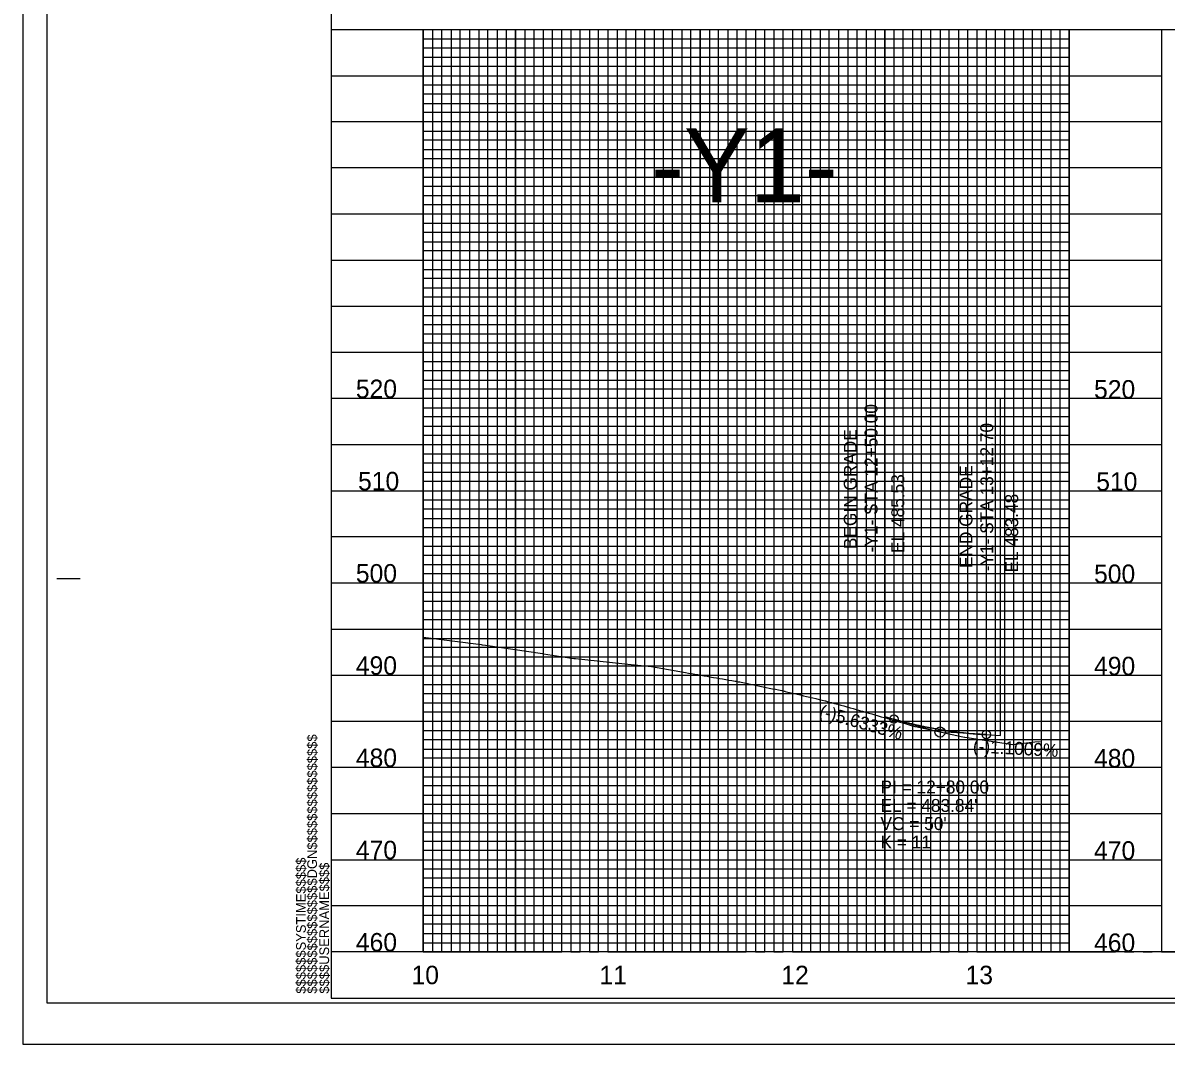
# Model space of a CAD drawing. Extents: x 571503 to 593215, y -77195 to -51828.
# Drawn here: x 582330 to 582949, y -75605 to -75051 of the extents above; entities that cross this region are included whole.
import ezdxf

# ---------------------------------------------------------------- set-up
doc = ezdxf.new("R2010")
doc.units = 0
for name, color, linetype in [('Exist Vertical Profile Ground Line', 7, 'Continuous'), ('Exist Vertical Profile Horizontal Axis Label Major', 7, 'Continuous'), ('Exist Vertical Profile Vertical Axis Label', 7, 'Continuous'), ('Prop PFL Text', 7, 'Continuous'), ('Prop Vertical Profile Curve Label', 7, 'Continuous'), ('Prop Vertical Profile Grade', 7, 'Continuous'), ('Prop Vertical Profile Grade Label', 7, 'Continuous'), ('Prop VPI Label', 7, 'Continuous'), ('Sheet Cutting Line CELL', 7, 'Continuous'), ('Sheet DOT Grid CELL', 7, 'Continuous'), ('Sheet Layout Profile Border Port 2', 7, 'Continuous'), ('Sheet Plot Border Inside CELL', 7, 'Continuous'), ('Sheet Plot Border Outside CELL', 7, 'Continuous'), ('Sheet Profile CELL', 7, 'Continuous'), ('Sheet Profile Grid Major CELL', 7, 'Continuous'), ('Sheet Profile Grid Middle CELL', 7, 'Continuous'), ('Sheet Profile Grid Minor CELL', 7, 'Continuous')]:
    doc.layers.add(name, color=color, linetype=linetype)

msp = doc.modelspace()

# ---------------------------------------------------------------- linework, layer by layer
at = {"layer": 'Exist Vertical Profile Ground Line'}
for points in [[(582546.98, -75384.54), (582578.29, -75388.57), (582578.94, -75388.65), (582580.68, -75388.87), (582611.64, -75393.46), (582611.65, -75393.47), (582612.17, -75393.54), (582628.61, -75396), (582629.52, -75396.11), (582661.19, -75399.46), (582661.41, -75399.49), (582670.54, -75400.46), (582670.58, -75400.46), (582688.97, -75403.68), (582690.65, -75403.97), (582692.34, -75404.26), (582694.02, -75404.56), (582695.71, -75404.85), (582697.39, -75405.15), (582699.07, -75405.44), (582700.76, -75405.73), (582701.53, -75405.87), (582702.44, -75406.02), (582703.17, -75406.14), (582704.13, -75406.31), (582705.81, -75406.6), (582707.49, -75406.9), (582709.18, -75407.19), (582710.86, -75407.48), (582712.55, -75407.78), (582714.23, -75408.07), (582715.92, -75408.37), (582716.27, -75408.43), (582717.6, -75408.67), (582718.09, -75408.75), (582718.42, -75408.82), (582719.28, -75409), (582720.97, -75409.34), (582722.65, -75409.68), (582724.34, -75410.02), (582726.02, -75410.37), (582727.71, -75410.71), (582729.39, -75411.06), (582731.07, -75411.41), (582732.76, -75411.75), (582734.44, -75412.1), (582736.13, -75412.45), (582737.81, -75412.8), (582739.5, -75413.15), (582741.18, -75413.5), (582742.51, -75413.78), (582742.86, -75413.88), (582743.03, -75413.93), (582744.55, -75414.28), (582746.23, -75414.67), (582747.92, -75415.06), (582749.6, -75415.45), (582751.29, -75415.85), (582752.97, -75416.24), (582754.65, -75416.64), (582756.34, -75417.04), (582758.02, -75417.43), (582759.71, -75417.83), (582761.39, -75418.24), (582763.08, -75418.64), (582764.76, -75419.04), (582764.87, -75419.07), (582766.44, -75419.53), (582766.97, -75419.69), (582768.13, -75420.01), (582768.68, -75420.16), (582769.81, -75420.47), (582771.5, -75420.92), (582773.18, -75421.37), (582774.86, -75421.83), (582776.55, -75422.29), (582777.75, -75422.62), (582778.23, -75422.76), (582779.92, -75423.24), (582781.6, -75423.73), (582783.29, -75424.21), (582784.97, -75424.7), (582786.65, -75425.19), (582788.34, -75425.67), (582790.02, -75426.16), (582791.71, -75426.65), (582793.39, -75427.14), (582795.08, -75427.63), (582796.76, -75428.11), (582798.13, -75428.51), (582798.44, -75428.59), (582798.63, -75428.63), (582800.13, -75429.07), (582801.81, -75429.56), (582803.5, -75430.05), (582805.18, -75430.54), (582806.87, -75431.04), (582808.55, -75431.53), (582810.23, -75432.02), (582811.92, -75432.52), (582811.98, -75432.54)], [(582811.98, -75432.54), (582813.24, -75432.92), (582813.41, -75432.96), (582813.6, -75433), (582815.29, -75433.36), (582816.97, -75433.72), (582818.66, -75434.09), (582820.34, -75434.45), (582839.28, -75438.56), (582840.19, -75438.75), (582840.43, -75438.73), (582866.36, -75442.67), (582867.62, -75442.56), (582869.06, -75442.36), (582878.4, -75441.23), (582881.23, -75441.07)]]:
    msp.add_lwpolyline(points, dxfattribs=at)
at = {"layer": 'Prop PFL Text'}
for p, q in [((582796.98, -75427.51), (582796.98, -75244.45)), ((582859.68, -75437.76), (582859.68, -75254.7))]:
    msp.add_line(p, q, dxfattribs=at)
at = {"layer": 'Prop Vertical Profile Curve Label'}
for centre in [(582801.98, -75428.92), (582851.98, -75437.34)]:
    msp.add_circle(centre, 2.25, dxfattribs=at)
at = {"layer": 'Prop Vertical Profile Grade'}
for p, q in [((582796.98, -75427.51), (582801.98, -75428.92)), ((582851.98, -75437.34), (582859.68, -75437.76))]:
    msp.add_line(p, q, dxfattribs=at)
msp.add_spline([(582801.98, -75428.92), (582802.98, -75429.2), (582803.98, -75429.47), (582804.98, -75429.74), (582805.98, -75430.01), (582806.98, -75430.27), (582807.98, -75430.53), (582808.98, -75430.78), (582809.98, -75431.03), (582810.98, -75431.27), (582811.98, -75431.51), (582812.98, -75431.74), (582813.98, -75431.97), (582814.98, -75432.2), (582815.98, -75432.42), (582816.98, -75432.64), (582817.98, -75432.85), (582818.98, -75433.05), (582819.98, -75433.26), (582820.98, -75433.45), (582821.98, -75433.65), (582822.98, -75433.84), (582823.98, -75434.02), (582824.98, -75434.2), (582825.98, -75434.37), (582826.98, -75434.55), (582827.98, -75434.71), (582828.98, -75434.87), (582829.98, -75435.03), (582830.98, -75435.18), (582831.98, -75435.33), (582832.98, -75435.47), (582833.98, -75435.61), (582834.98, -75435.75), (582835.98, -75435.88), (582836.98, -75436), (582837.98, -75436.12), (582838.98, -75436.24), (582839.98, -75436.35), (582840.98, -75436.46), (582841.98, -75436.56), (582842.98, -75436.66), (582843.98, -75436.75), (582844.98, -75436.84), (582845.98, -75436.93), (582846.98, -75437.01), (582847.98, -75437.08), (582848.98, -75437.15), (582849.98, -75437.22), (582850.98, -75437.28), (582851.98, -75437.34)], degree=3, dxfattribs=at)
at = {"layer": 'Prop VPI Label'}
for p, q in [((582801.98, -75428.92), (582824.34, -75435.22)), ((582851.98, -75437.34), (582829.73, -75436.11))]:
    msp.add_line(p, q, dxfattribs=at)
msp.add_circle((582826.98, -75435.96), 2.75, dxfattribs=at)
at = {"layer": 'Sheet Cutting Line CELL'}
for p, q in [((582329.98, -74505.16), (582329.98, -75605.16)), ((582329.98, -75605.16), (584013.98, -75605.16))]:
    msp.add_line(p, q, dxfattribs=at)
at = {"layer": 'Sheet DOT Grid CELL'}
for p, q in [((582496.98, -75055.16), (583996.87, -75055.16)), ((582546.98, -75055.16), (582546.98, -75555.16)), ((582596.98, -75055.16), (582596.98, -75555.16)), ((582646.98, -75055.16), (582646.98, -75555.16)), ((582696.98, -75055.16), (582696.98, -75555.16)), ((582746.98, -75055.16), (582746.98, -75555.16)), ((582796.98, -75055.16), (582796.98, -75555.16)), ((582846.98, -75055.16), (582846.98, -75555.16)), ((582896.98, -75055.16), (582896.98, -75555.16)), ((582946.98, -75055.16), (582946.98, -75555.16))]:
    msp.add_line(p, q, dxfattribs=at)
at = {"layer": 'Sheet Layout Profile Border Port 2'}
msp.add_lwpolyline([(582546.98, -75055.16), (583946.98, -75055.16), (583946.98, -75555.16), (582546.98, -75555.16)], close=True, dxfattribs=at)
at = {"layer": 'Sheet Plot Border Inside CELL'}
msp.add_lwpolyline([(582342.98, -75582.71), (584009.48, -75582.71), (584009.48, -74527.61), (582342.98, -74527.61)], close=True, dxfattribs=at)
at = {"layer": 'Sheet Plot Border Outside CELL'}
msp.add_lwpolyline([(582329.98, -75605.16), (584013.98, -75605.16), (584013.98, -74505.16), (582329.98, -74505.16)], close=True, dxfattribs=at)
at = {"layer": 'Sheet Profile CELL'}
for p, q in [((582496.98, -75055.16), (583996.98, -75055.16)), ((582348.48, -75352.66), (582360.98, -75352.66)), ((583996.98, -75555.16), (582496.98, -75555.16)), ((582496.98, -75580.16), (583996.98, -75580.16)), ((582496.98, -75580.16), (582496.98, -75580.16)), ((582496.98, -75580.16), (582496.98, -75580.16)), ((582496.98, -75580.16), (582496.98, -75580.16)), ((582496.98, -75580.16), (582496.98, -75580.16)), ((582496.98, -75580.16), (582496.98, -75580.16)), ((582496.98, -75580.16), (582496.98, -75580.16)), ((582496.98, -75580.16), (582496.98, -75580.16))]:
    msp.add_line(p, q, dxfattribs=at)
msp.add_lwpolyline([(583996.98, -74530.16), (582496.98, -74530.16), (582496.98, -75580.16), (583996.98, -75580.16)], close=True, dxfattribs=at)
msp.add_lwpolyline([(582534.48, -75580.16), (582534.48, -75580.16)], dxfattribs=at)
at = {"layer": 'Sheet Profile Grid Major CELL'}
for p, q in [((582546.98, -75055.16), (582546.98, -75555.16)), ((582596.98, -75555.16), (582596.98, -75055.16)), ((582596.98, -75055.16), (582646.98, -75055.16)), ((582646.98, -75055.16), (582646.98, -75555.16)), ((582696.98, -75555.16), (582696.98, -75055.16)), ((582696.98, -75055.16), (582746.98, -75055.16)), ((582746.98, -75055.16), (582746.98, -75555.16)), ((582796.98, -75555.16), (582796.98, -75055.16)), ((582796.98, -75055.16), (582846.98, -75055.16)), ((582846.98, -75055.16), (582846.98, -75555.16)), ((582896.98, -75555.16), (582896.98, -75055.16)), ((582896.98, -75055.16), (582946.98, -75055.16)), ((582946.98, -75055.16), (582946.98, -75555.16)), ((582496.98, -75455.16), (582496.98, -75455.16)), ((582496.98, -75455.16), (582496.98, -75505.16)), ((582946.98, -75455.16), (582496.98, -75455.16)), ((582496.98, -75505.16), (582946.98, -75505.16)), ((582496.98, -75555.16), (582496.98, -75555.16)), ((582546.98, -75555.16), (582596.98, -75555.16)), ((582646.98, -75555.16), (582696.98, -75555.16)), ((582746.98, -75555.16), (582796.98, -75555.16)), ((582846.98, -75555.16), (582896.98, -75555.16)), ((582946.98, -75555.16), (582996.98, -75555.16))]:
    msp.add_line(p, q, dxfattribs=at)
for points in [[(582946.98, -75105.16), (582496.98, -75105.16)], [(582946.98, -75155.16), (582496.98, -75155.16), (582496.98, -75205.16), (582946.98, -75205.16)], [(582946.98, -75255.16), (582496.98, -75255.16), (582496.98, -75305.16), (582946.98, -75305.16)], [(582946.98, -75355.16), (582496.98, -75355.16), (582496.98, -75405.16), (582946.98, -75405.16)], [(583996.98, -75555.16), (582496.98, -75555.16)]]:
    msp.add_lwpolyline(points, dxfattribs=at)
at = {"layer": 'Sheet Profile Grid Middle CELL'}
for p, q in [((582521.98, -75055.16), (582571.98, -75055.16)), ((582571.98, -75055.16), (582571.98, -75555.16)), ((582621.98, -75555.16), (582621.98, -75055.16)), ((582621.98, -75055.16), (582671.98, -75055.16)), ((582671.98, -75055.16), (582671.98, -75555.16)), ((582721.98, -75555.16), (582721.98, -75055.16)), ((582721.98, -75055.16), (582771.98, -75055.16)), ((582771.98, -75055.16), (582771.98, -75555.16)), ((582821.98, -75555.16), (582821.98, -75055.16)), ((582821.98, -75055.16), (582871.98, -75055.16)), ((582871.98, -75055.16), (582871.98, -75555.16)), ((582921.98, -75055.16), (582971.98, -75055.16)), ((582571.98, -75555.16), (582621.98, -75555.16)), ((582671.98, -75555.16), (582721.98, -75555.16)), ((582771.98, -75555.16), (582821.98, -75555.16)), ((582871.98, -75555.16), (582921.98, -75555.16))]:
    msp.add_line(p, q, dxfattribs=at)
for points in [[(582496.98, -75080.16), (582946.98, -75080.16)], [(582946.98, -75130.16), (582496.98, -75130.16), (582496.98, -75180.16), (582946.98, -75180.16)], [(582946.98, -75230.16), (582496.98, -75230.16), (582496.98, -75280.16), (582946.98, -75280.16)], [(582946.98, -75330.16), (582496.98, -75330.16), (582496.98, -75380.16), (582946.98, -75380.16)], [(582946.98, -75430.16), (582496.98, -75430.16), (582496.98, -75480.16), (582946.98, -75480.16)], [(582946.98, -75530.16), (582496.98, -75530.16)]]:
    msp.add_lwpolyline(points, dxfattribs=at)
at = {"layer": 'Sheet Profile Grid Minor CELL'}
for p, q in [((582766.98, -75555.16), (582766.98, -75055.16)), ((582766.98, -75055.16), (582776.98, -75055.16)), ((582776.98, -75055.16), (582776.98, -75555.16)), ((582781.98, -75555.16), (582781.98, -75055.16)), ((582781.98, -75055.16), (582786.98, -75055.16)), ((582786.98, -75055.16), (582786.98, -75555.16)), ((582791.98, -75555.16), (582791.98, -75055.16)), ((582791.98, -75055.16), (582801.98, -75055.16)), ((582801.98, -75055.16), (582801.98, -75555.16)), ((582806.98, -75555.16), (582806.98, -75055.16)), ((582806.98, -75055.16), (582811.98, -75055.16)), ((582811.98, -75055.16), (582811.98, -75555.16)), ((582816.98, -75555.16), (582816.98, -75055.16)), ((582816.98, -75055.16), (582826.98, -75055.16)), ((582826.98, -75055.16), (582826.98, -75555.16)), ((582831.98, -75555.16), (582831.98, -75055.16)), ((582831.98, -75055.16), (582836.98, -75055.16)), ((582836.98, -75055.16), (582836.98, -75555.16)), ((582841.98, -75555.16), (582841.98, -75055.16)), ((582841.98, -75055.16), (582851.98, -75055.16)), ((582851.98, -75055.16), (582851.98, -75555.16)), ((582856.98, -75555.16), (582856.98, -75055.16)), ((582856.98, -75055.16), (582861.98, -75055.16)), ((582861.98, -75055.16), (582861.98, -75555.16)), ((582866.98, -75555.16), (582866.98, -75055.16)), ((582866.98, -75055.16), (582876.98, -75055.16)), ((582876.98, -75055.16), (582876.98, -75555.16)), ((582881.98, -75555.16), (582881.98, -75055.16)), ((582881.98, -75055.16), (582886.98, -75055.16)), ((582886.98, -75055.16), (582886.98, -75555.16)), ((582891.98, -75555.16), (582891.98, -75055.16)), ((582891.98, -75055.16), (582901.98, -75055.16)), ((582906.98, -75055.16), (582911.98, -75055.16)), ((582916.98, -75055.16), (582926.98, -75055.16)), ((582931.98, -75055.16), (582936.98, -75055.16)), ((582941.98, -75055.16), (582951.98, -75055.16)), ((582546.98, -75060.16), (582896.98, -75060.16)), ((582896.98, -75065.16), (582546.98, -75065.16)), ((582546.98, -75070.16), (582896.98, -75070.16)), ((582896.98, -75075.16), (582546.98, -75075.16)), ((582546.98, -75085.16), (582896.98, -75085.16)), ((582896.98, -75090.16), (582546.98, -75090.16)), ((582546.98, -75095.16), (582896.98, -75095.16)), ((582896.98, -75100.16), (582546.98, -75100.16)), ((582546.98, -75110.16), (582896.98, -75110.16)), ((582896.98, -75115.16), (582546.98, -75115.16)), ((582546.98, -75120.16), (582896.98, -75120.16)), ((582896.98, -75125.16), (582546.98, -75125.16)), ((582546.98, -75135.16), (582896.98, -75135.16)), ((582896.98, -75140.16), (582546.98, -75140.16)), ((582546.98, -75145.16), (582896.98, -75145.16)), ((582896.98, -75150.16), (582546.98, -75150.16)), ((582546.98, -75160.16), (582896.98, -75160.16)), ((582896.98, -75165.16), (582546.98, -75165.16)), ((582546.98, -75170.16), (582896.98, -75170.16)), ((582896.98, -75175.16), (582546.98, -75175.16)), ((582546.98, -75185.16), (582896.98, -75185.16)), ((582896.98, -75190.16), (582546.98, -75190.16)), ((582546.98, -75195.16), (582896.98, -75195.16)), ((582896.98, -75200.16), (582546.98, -75200.16)), ((582546.98, -75210.16), (582896.98, -75210.16)), ((582896.98, -75215.16), (582546.98, -75215.16)), ((582546.98, -75220.16), (582896.98, -75220.16)), ((582896.98, -75225.16), (582546.98, -75225.16)), ((582546.98, -75235.16), (582896.98, -75235.16)), ((582896.98, -75240.16), (582546.98, -75240.16)), ((582546.98, -75245.16), (582896.98, -75245.16)), ((582896.98, -75250.05), (582546.98, -75250.01)), ((582546.98, -75260.16), (582896.98, -75260.16)), ((582896.98, -75265.16), (582546.98, -75265.16)), ((582546.98, -75270.16), (582896.98, -75270.16)), ((582896.98, -75275.16), (582546.98, -75275.16)), ((582546.98, -75285.16), (582896.98, -75285.16)), ((582896.98, -75290.16), (582546.98, -75290.16)), ((582546.98, -75295.16), (582896.98, -75295.16)), ((582896.98, -75300.16), (582546.98, -75300.16)), ((582546.98, -75310.16), (582896.98, -75310.16)), ((582896.98, -75315.16), (582546.98, -75315.16)), ((582546.98, -75320.16), (582896.98, -75320.16)), ((582896.98, -75325.16), (582546.98, -75325.16)), ((582546.98, -75335.16), (582896.98, -75335.16)), ((582896.98, -75340.16), (582546.98, -75340.16)), ((582546.98, -75345.16), (582896.98, -75345.16)), ((582896.98, -75350.16), (582546.98, -75350.16)), ((582546.98, -75360.16), (582896.98, -75360.16)), ((582896.98, -75365.16), (582546.98, -75365.16)), ((582546.98, -75370.16), (582896.98, -75370.16)), ((582896.98, -75375.16), (582546.98, -75375.16)), ((582546.98, -75385.16), (582896.98, -75385.16)), ((582896.98, -75390.16), (582546.98, -75390.16)), ((582546.98, -75395.16), (582896.98, -75395.16)), ((582896.98, -75400.16), (582546.98, -75400.16)), ((582546.98, -75410.16), (582896.98, -75410.16)), ((582896.98, -75415.16), (582546.98, -75415.16)), ((582546.98, -75420.16), (582896.98, -75420.16)), ((582896.98, -75425.16), (582546.98, -75425.16)), ((582546.98, -75435.16), (582896.98, -75435.16)), ((582896.98, -75440.16), (582546.98, -75440.16)), ((582546.98, -75445.16), (582896.98, -75445.16)), ((582896.98, -75450.16), (582546.98, -75450.16)), ((582546.98, -75460.16), (582896.98, -75460.16)), ((582896.98, -75465.16), (582546.98, -75465.16)), ((582546.98, -75470.16), (582896.98, -75470.16)), ((582896.98, -75475.16), (582546.98, -75475.16)), ((582546.98, -75485.16), (582896.98, -75485.16)), ((582896.98, -75490.16), (582546.98, -75490.16)), ((582546.98, -75495.16), (582896.98, -75495.16)), ((582896.98, -75500.16), (582546.98, -75500.16)), ((582546.98, -75510.16), (582896.98, -75510.16)), ((582896.98, -75515.16), (582546.98, -75515.16)), ((582546.98, -75520.16), (582896.98, -75520.16)), ((582896.98, -75525.16), (582546.98, -75525.16)), ((582546.98, -75535.16), (582896.98, -75535.16)), ((582896.98, -75540.16), (582546.98, -75540.16)), ((582546.98, -75545.16), (582896.98, -75545.16)), ((582546.98, -75550.16), (582896.98, -75550.16)), ((582761.98, -75555.16), (582766.98, -75555.16)), ((582776.98, -75555.16), (582781.98, -75555.16)), ((582786.98, -75555.16), (582791.98, -75555.16)), ((582801.98, -75555.16), (582806.98, -75555.16)), ((582811.98, -75555.16), (582816.98, -75555.16)), ((582826.98, -75555.16), (582831.98, -75555.16)), ((582836.98, -75555.16), (582841.98, -75555.16)), ((582851.98, -75555.16), (582856.98, -75555.16)), ((582861.98, -75555.16), (582866.98, -75555.16)), ((582876.98, -75555.16), (582881.98, -75555.16)), ((582886.98, -75555.16), (582891.98, -75555.16)), ((582901.98, -75555.16), (582906.98, -75555.16)), ((582911.98, -75555.16), (582916.98, -75555.16)), ((582926.98, -75555.16), (582931.98, -75555.16)), ((582936.98, -75555.16), (582941.98, -75555.16))]:
    msp.add_line(p, q, dxfattribs=at)
for points in [[(582546.98, -75055.16), (582551.98, -75055.16), (582551.98, -75555.16), (582556.98, -75555.16), (582556.98, -75055.16), (582561.98, -75055.16), (582561.98, -75555.16), (582566.98, -75555.16), (582566.98, -75055.16), (582576.98, -75055.16), (582576.98, -75555.16), (582581.98, -75555.16), (582581.98, -75055.16), (582586.98, -75055.16), (582586.98, -75555.16), (582591.98, -75555.16), (582601.98, -75555.16), (582606.98, -75555.16), (582606.98, -75055.16), (582611.98, -75055.16), (582611.98, -75555.16), (582616.98, -75555.16), (582616.98, -75055.16), (582626.98, -75055.16), (582626.98, -75555.16), (582631.98, -75555.16), (582631.98, -75055.16), (582636.98, -75055.16), (582636.98, -75555.16), (582641.98, -75555.16), (582641.98, -75055.16), (582651.98, -75055.16), (582651.98, -75555.16), (582656.98, -75555.16), (582656.98, -75055.16), (582661.98, -75055.16), (582661.98, -75555.16), (582666.98, -75555.16), (582666.98, -75055.16), (582676.98, -75055.16), (582676.98, -75555.16), (582681.98, -75555.16), (582681.98, -75055.16), (582686.98, -75055.16), (582686.98, -75555.16), (582691.98, -75555.16), (582691.98, -75055.16), (582701.98, -75055.16), (582701.98, -75555.16), (582706.98, -75555.16), (582706.98, -75055.16), (582711.98, -75055.16), (582711.98, -75555.16), (582716.98, -75555.16), (582716.98, -75055.16), (582726.98, -75055.16), (582726.98, -75555.16), (582731.98, -75555.16), (582731.98, -75055.16), (582736.98, -75055.16), (582736.98, -75555.16), (582741.98, -75555.16), (582741.98, -75055.16), (582751.98, -75055.16), (582751.98, -75555.16), (582756.98, -75555.16), (582756.98, -75055.16), (582761.98, -75055.16), (582761.98, -75555.16)], [(582591.98, -75555.16), (582591.98, -75055.16), (582601.98, -75055.16), (582601.98, -75555.16)]]:
    msp.add_lwpolyline(points, dxfattribs=at)

# ---------------------------------------------------------------- texts
at = {"layer": 'Exist Vertical Profile Horizontal Axis Label Major'}
for s, p in [('10', (582540.57, -75572.66)), ('11', (582642.41, -75572.66)), ('12', (582740.95, -75572.66)), ('13', (582840.79, -75572.66))]:
    msp.add_text(s, height=10, dxfattribs=at).set_placement(p)
at = {"layer": 'Exist Vertical Profile Vertical Axis Label'}
for s, height, p in [('-Y1-', 40, (582670.4, -75148.75)), ('520', 10, (582510.42, -75254.91)), ('520', 10, (582910.42, -75255.16)), ('510', 10, (582511.61, -75304.91)), ('510', 10, (582911.61, -75305.16)), ('500', 10, (582510.42, -75354.91)), ('500', 10, (582910.42, -75355.16)), ('490', 10, (582510.42, -75404.91)), ('490', 10, (582910.42, -75405.16)), ('480', 10, (582510.42, -75454.91)), ('480', 10, (582910.42, -75455.16)), ('470', 10, (582510.42, -75504.91)), ('470', 10, (582910.42, -75505.16)), ('460', 10, (582510.42, -75554.91)), ('460', 10, (582910.42, -75555.16))]:
    msp.add_text(s, height=height, dxfattribs=at).set_placement(p)
at = {"layer": 'Prop PFL Text'}
for s, p in [('-Y1- STA 12+50.00', (582793.09, -75338.54)), ('-Y1- STA 13+12.70', (582855.79, -75348.79)), ('BEGIN GRADE', (582781.84, -75336.79)), ('END GRADE', (582844.54, -75347.04)), ('EL 485.53', (582807.56, -75338.86)), ('EL 483.48', (582869.3, -75349.47))]:
    msp.add_text(s, height=7, rotation=90, dxfattribs=at).set_placement(p)
at = {"layer": 'Prop Vertical Profile Grade Label'}
for s, rotation, p in [('(-)5.6333%', 344.26924, (582760.95, -75427.75)), ('(-)1.1009%', 356.84933, (582844.64, -75446.95))]:
    msp.add_text(s, height=7, rotation=rotation, dxfattribs=at).set_placement(p)
at = {"layer": 'Prop VPI Label'}
for s, p in [('PI = 12+80.00', (582794.7, -75469.26)), ("EL = 483.84'", (582794.7, -75479.26)), ("VC = 50'", (582794.7, -75489.09)), ('K = 11', (582794.7, -75499.09))]:
    msp.add_text(s, height=7, dxfattribs=at).set_placement(p)
at = {"layer": 'Sheet Profile CELL'}
for s, p in [('$$$$$$$$$$$$$$$$DGN$$$$$$$$$$$$$$$$', (582489.35, -75577.79)), ('$$$$$$SYSTIME$$$$$', (582483.3, -75577.79)), ('$$$$USERNAME$$$$', (582495.92, -75577.77))]:
    msp.add_text(s, height=5.25, rotation=90, dxfattribs=at).set_placement(p)

doc.saveas('drawing.dxf')
